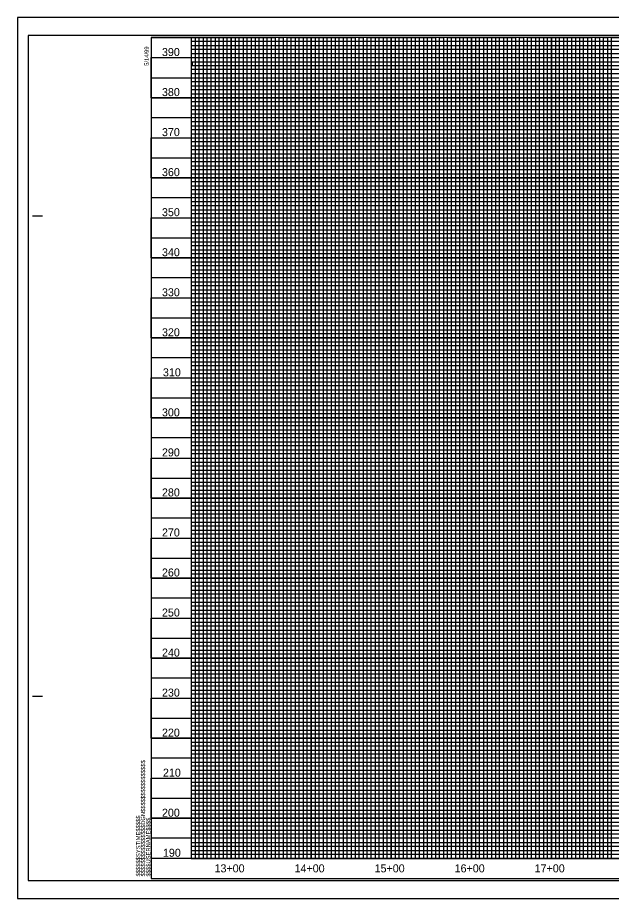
# Model space of a CAD drawing. Extents: x 10033 to 11717, y 9950 to 11050.
# Drawn here: x 10033 to 10775, y 9950 to 11050 of the extents above; entities that cross this region are included whole.
import ezdxf

# ---------------------------------------------------------------- set-up
doc = ezdxf.new("R2010")
doc.units = 0
for name, color, linetype in [('Exist Vertical Profile Horizontal Axis Label Major', 7, 'Continuous'), ('Exist Vertical Profile Vertical Axis Label', 7, 'Continuous'), ('Sheet Cutting Line CELL', 7, 'Continuous'), ('Sheet DOT Grid CELL', 7, 'Continuous'), ('Sheet Layout Profile Border', 7, 'Continuous'), ('Sheet Plot Border Inside CELL', 7, 'Continuous'), ('Sheet Plot Border Outside CELL', 7, 'Continuous'), ('Sheet Profile CELL', 7, 'Continuous'), ('Sheet Profile Grid Major CELL', 7, 'Continuous'), ('Sheet Profile Grid Middle CELL', 7, 'Continuous'), ('Sheet Profile Grid Minor CELL', 7, 'Continuous')]:
    doc.layers.add(name, color=color, linetype=linetype)

msp = doc.modelspace()

# ---------------------------------------------------------------- linework, layer by layer
at = {"layer": 'Sheet Cutting Line CELL'}
for p, q in [((11717, 11050), (10033, 11050)), ((10033, 11050), (10033, 9950)), ((10033, 9950), (11717, 9950))]:
    msp.add_line(p, q, dxfattribs=at)
at = {"layer": 'Sheet DOT Grid CELL'}
for p, q in [((10250, 11025), (10250, 10000)), ((10300, 11025), (10300, 10000)), ((10350, 11025), (10350, 10000)), ((10400, 11025), (10400, 10000)), ((10450, 11025), (10450, 10000)), ((10500, 11025), (10500, 10000)), ((10550, 11025), (10550, 10000)), ((10600, 11025), (10600, 10000)), ((10650, 11025), (10650, 10000)), ((10700, 11025), (10700, 10000)), ((10750, 11025), (10750, 10000)), ((10200, 11000), (11500, 11000)), ((10200, 10950), (11500, 10950)), ((10200, 10900), (11500, 10900)), ((10200, 10850), (11700, 10850)), ((10200, 10800), (11700, 10800)), ((10200, 10750), (11700, 10750)), ((10200, 10700), (11700, 10700)), ((10200, 10650), (11700, 10650)), ((10200, 10600), (11700, 10600)), ((10200, 10550), (11700, 10550)), ((10200, 10500), (11700, 10500)), ((10200, 10450), (11700, 10450)), ((10200, 10400), (11700, 10400)), ((10200, 10350), (11700, 10350)), ((10200, 10300), (11700, 10300)), ((10200, 10250), (11700, 10250)), ((10200, 10200), (11700, 10200)), ((10200, 10150), (11700, 10150)), ((10200, 10100), (11700, 10100)), ((10200, 10050), (11700, 10050))]:
    msp.add_line(p, q, dxfattribs=at)
at = {"layer": 'Sheet Layout Profile Border'}
msp.add_lwpolyline([(10250, 11025), (10250, 10000), (11650, 10000), (11650, 10887.5), (11500, 10887.5), (11500, 11025)], close=True, dxfattribs=at)
at = {"layer": 'Sheet Plot Border Inside CELL'}
msp.add_lwpolyline([(11712.5, 11027.6), (10046, 11027.6), (10046, 9972.5), (11712.5, 9972.5)], close=True, dxfattribs=at)
at = {"layer": 'Sheet Plot Border Outside CELL'}
msp.add_lwpolyline([(11717, 11050), (10033, 11050), (10033, 9950), (11717, 9950)], close=True, dxfattribs=at)
at = {"layer": 'Sheet Profile CELL'}
for p, q in [((10051.5, 10802.5), (10064, 10802.5)), ((10051.5, 10202.5), (10064, 10202.5)), ((11700, 10000), (10200, 10000)), ((10200, 9975), (10200, 9975)), ((10200, 9975), (10200, 9975)), ((10200, 9975), (10200, 9975)), ((10200, 9975), (10200, 9975)), ((10200, 9975), (10200, 9975)), ((10200, 9975), (10200, 9975))]:
    msp.add_line(p, q, dxfattribs=at)
msp.add_lwpolyline([(11700, 11025), (10200, 11025), (10200, 9975), (11700, 9975)], close=True, dxfattribs=at)
msp.add_lwpolyline([(10237.5, 9975), (10237.5, 9975)], dxfattribs=at)
at = {"layer": 'Sheet Profile Grid Major CELL'}
for points in [[(10200, 11025), (10250, 11025), (10250, 10000), (10300, 10000), (10300, 11025), (10350, 11025), (10350, 10000), (10400, 10000), (10400, 11025), (10450, 11025), (10450, 10000), (10500, 10000), (10500, 11025), (10550, 11025), (10550, 10000), (10600, 10000), (10600, 11025), (10650, 11025), (10650, 10000), (10700, 10000), (10700, 11025), (10750, 11025), (10750, 10000), (10800, 10000)], [(11500, 10950), (10200.1, 10950), (10200.1, 11000), (11500, 11000)], [(11700, 10850), (10200, 10850), (10200, 10900), (11500, 10900)], [(11700, 10750), (10200, 10750), (10200, 10800), (11700, 10800)], [(11700, 10650), (10200, 10650), (10200, 10700), (11700, 10700)], [(11700, 10550), (10200, 10550), (10200, 10600), (11700, 10600)], [(11700, 10450), (10200, 10450), (10200, 10500), (11700, 10500)], [(11700, 10350), (10200, 10350), (10200, 10400), (11700, 10400)], [(11700, 10250), (10200, 10250), (10200, 10300), (11700, 10300)], [(11700, 10150), (10200, 10150), (10200, 10200), (11700, 10200)], [(11700, 10050), (10200, 10050), (10200, 10100), (11700, 10100)]]:
    msp.add_lwpolyline(points, dxfattribs=at)
at = {"layer": 'Sheet Profile Grid Middle CELL'}
for points in [[(10275, 10000), (10275, 11025), (10325, 11025), (10325, 10000), (10375, 10000), (10375, 11025), (10425, 11025), (10425, 10000), (10475, 10000), (10475, 11025), (10525, 11025), (10525, 10000), (10575, 10000), (10575, 11025), (10625, 11025), (10625, 10000), (10675, 10000), (10675, 11025), (10725, 11025), (10725, 10000), (10775, 10000), (10775, 11025), (10825, 11025)], [(10200, 10975), (11500, 10975)], [(11500, 10925), (10200, 10925), (10200, 10875), (11700, 10875)], [(11700, 10825), (10200, 10825), (10200, 10775), (11700, 10775)], [(11700, 10725), (10200, 10725), (10200, 10675), (11700, 10675)], [(11700, 10625), (10200, 10625), (10200, 10575), (11700, 10575)], [(11700, 10525), (10200, 10525), (10200, 10475), (11700, 10475)], [(11700, 10425), (10200, 10425), (10200, 10375), (11700, 10375)], [(11700, 10325), (10200, 10325), (10200, 10275), (11700, 10275)], [(11700, 10225), (10200, 10225), (10200, 10175), (11700, 10175)], [(11700, 10125), (10200, 10125), (10200, 10075), (11700, 10075)], [(11700, 10025), (10200, 10025)]]:
    msp.add_lwpolyline(points, dxfattribs=at)
at = {"layer": 'Sheet Profile Grid Minor CELL'}
for p, q in [((11650, 10845), (10250, 10845)), ((10250, 10845), (10250, 10840)), ((10250, 10840), (11650, 10840)), ((11650, 10820), (10250, 10820))]:
    msp.add_line(p, q, dxfattribs=at)
for points in [[(10255, 11025), (10260, 11025), (10265, 11025), (10270, 11025), (10280, 11025), (10247, 11025), (10252, 11025), (10210, 11025), (10215, 11025), (10220, 11025), (10230, 11025), (10235, 11025), (10240, 11025), (10245, 11025), (10255, 11025), (10255, 10000), (10260, 10000), (10260, 11025), (10265, 11025), (10265, 10000), (10270, 10000), (10270, 11025), (10280, 11025), (10280, 10000), (10285, 10000), (10285, 11025), (10290, 11025), (10290, 10000), (10295, 10000), (10295, 11025), (10305, 11025), (10305, 10000), (10310, 10000), (10310, 11025), (10315, 11025), (10315, 10000), (10320, 10000), (10320, 11025), (10330, 11025), (10330, 10000), (10335, 10000), (10335, 11025), (10340, 11025), (10340, 10000), (10345, 10000), (10345, 11025), (10355, 11025), (10355, 10000), (10360, 10000), (10360, 11025), (10365, 11025), (10365, 10000), (10370, 10000), (10370, 11025), (10380, 11025), (10380, 10000), (10385, 10000), (10385, 11025), (10390, 11025), (10390, 10000), (10395, 10000), (10395, 11025), (10405, 11025), (10405, 10000), (10410, 10000), (10410, 11025), (10415, 11025), (10415, 10000)], [(10415, 10000), (10420, 10000), (10420, 11025), (10430, 11025), (10430, 10000), (10435, 10000), (10435, 11025), (10440, 11025), (10440, 10000), (10445, 10000), (10445, 11025), (10455, 11025), (10455, 10000), (10460, 10000), (10460, 11025), (10460, 11025), (10465, 11025), (10465, 10000), (10470, 10000), (10470, 11025), (10480, 11025), (10480, 10000), (10485, 10000), (10485, 11025), (10490, 11025), (10490, 10000), (10495, 10000), (10495, 11025), (10505, 11025), (10505, 10000), (10510, 10000), (10510, 11025), (10515, 11025), (10515, 10000), (10520, 10000), (10520, 11025), (10530, 11025), (10530, 10000), (10535, 10000), (10535, 11025), (10540, 11025), (10540, 10000), (10545, 10000), (10545, 11025), (10555, 11025), (10555, 10000), (10560, 10000), (10560, 11025), (10565, 11025), (10565, 10000), (10570, 10000), (10570, 11025), (10580, 11025), (10580, 10000), (10595, 10000), (10595, 11025), (10605, 11025), (10605, 10000), (10610, 10000), (10610, 11025), (10615, 11025), (10615, 10000), (10620, 10000), (10620, 11025), (10630, 11025), (10630, 10000), (10635, 10000), (10635, 11025), (10640, 11025), (10640, 10000), (10645, 10000), (10645, 11025), (10655, 11025), (10655, 10000), (10660, 10000), (10660, 11025), (10665, 11025), (10665, 10000), (10670, 10000), (10670, 11025), (10680, 11025), (10680, 10000), (10685, 10000), (10685, 11025), (10690, 11025), (10690, 10000), (10695, 10000), (10695, 11025), (10705, 11025), (10705, 10000), (10710, 10000), (10710, 11025), (10715, 11025), (10715, 10000), (10720, 10000), (10720, 11025), (10730, 11025), (10730, 10000)], [(10585, 11025), (10585, 10000), (10590, 10000), (10590, 11025)], [(10585, 11024.4), (10585, 10000), (10590, 10000), (10590, 11024.4)], [(10735, 11025), (10735, 10000), (10740, 10000), (10740, 11025), (10745, 11025), (10745, 10000), (10755, 10000), (10755, 11025), (10760, 11025), (10760, 10000), (10765, 10000), (10765, 11025), (10770, 11025), (10770, 10000)], [(11500, 11020), (10250, 11020), (10250, 11015), (11500, 11015)], [(11500, 11010), (10250, 11010), (10250, 11005), (11500, 11005)], [(11500, 10994.2), (10251, 10994.2), (10251, 10990), (11500, 10990)], [(11500, 10985), (10250, 10985), (10250, 10980), (11500, 10980)], [(11500, 10970), (10250, 10970), (10250, 10965), (11500, 10965)], [(11500, 10960), (10250, 10960), (10250, 10955), (11500, 10955)], [(11500, 10945), (10250, 10945), (10250, 10940), (11500, 10940)], [(11500, 10935), (10250, 10935), (10250, 10930), (11500, 10930)], [(11500, 10920), (10250, 10920), (10250, 10915), (11500, 10915)], [(11500, 10910), (10250, 10910), (10250, 10905), (11500, 10905)], [(11500, 10895), (10250, 10895), (10250, 10890), (11500, 10890)], [(11650, 10885), (10250, 10885), (10250, 10885), (10250, 10865), (11650, 10865)], [(10250, 10880), (11650, 10880)], [(11650, 10870), (10250, 10870)], [(11650, 10860), (10250, 10860), (10250, 10855), (11650, 10855)], [(11650, 10835), (10250, 10835), (10250, 10830), (11650, 10830)], [(11650, 10815), (10250, 10815), (10250, 10810), (11650, 10810)], [(11650, 10805), (10250, 10805)], [(10250, 10795), (11650, 10795)], [(11650, 10790), (10250, 10790), (10250, 10785), (11650, 10785)], [(11650, 10780), (10250, 10780), (10250, 10770), (11650, 10770)], [(11650, 10765), (10250, 10765), (10250, 10760), (11650, 10760)], [(11650, 10755), (10250, 10755), (10250, 10745), (11650, 10745)], [(11650, 10740), (10250, 10740), (10250, 10735), (11650, 10735)], [(11650, 10730), (10250, 10730), (10250, 10720), (11650, 10720)], [(11650, 10715), (10250, 10715), (10250, 10710), (11650, 10710)], [(11650, 10705), (10250, 10705), (10250, 10695), (11650, 10695)], [(11650, 10690), (10250, 10690), (10250, 10685), (11650, 10685)], [(11650, 10680), (10250, 10680), (10250, 10670), (11650, 10670)], [(11650, 10665), (10250, 10665), (10250, 10660), (11650, 10660)], [(11650, 10655), (10250, 10655), (10250, 10645), (11650, 10645)], [(11650, 10640), (10250, 10640), (10250, 10635), (11650, 10635)], [(11650, 10630), (10250, 10630), (10250, 10620), (11650, 10620)], [(11650, 10615), (10250, 10615), (10250, 10610), (11650, 10610)], [(11650, 10605), (10250, 10605), (10250, 10595), (11650, 10595)], [(11650, 10590), (10250, 10590), (10250, 10585), (11650, 10585)], [(11650, 10580), (10250, 10580), (10250, 10570), (11650, 10570)], [(11650, 10565), (10250, 10565), (10250, 10560), (11650, 10560)], [(11650, 10555), (10250, 10555), (10250, 10545), (11650, 10545)], [(11650, 10540), (10250, 10540), (10250, 10535), (11650, 10535)], [(11650, 10530), (10250, 10530), (10250, 10520), (11650, 10520)], [(11650, 10515), (10250, 10515), (10250, 10510), (11650, 10510)], [(11650, 10505), (10250, 10505)], [(10250, 10495), (11650, 10495)], [(11650, 10490), (10250, 10490), (10250, 10485), (11650, 10485)], [(11650, 10480), (10250, 10480), (10250, 10470), (11650, 10470)], [(11650, 10465), (10250, 10465), (10250, 10460), (11650, 10460)], [(11650, 10455), (10250, 10455), (10250, 10445), (11650, 10445)], [(11650, 10440), (10250, 10440), (10250, 10435), (11650, 10435)], [(11650, 10430), (10250, 10430), (10250, 10420), (11650, 10420)], [(11650, 10415), (10250, 10415), (10250, 10410), (11650, 10410)], [(11650, 10405), (10250, 10405), (10250, 10395), (11650, 10395)], [(11650, 10390), (10250, 10390), (10250, 10385), (11650, 10385)], [(11650, 10380), (10250, 10380), (10250, 10370), (11650, 10370)], [(11650, 10365), (10250, 10365), (10250, 10360), (11650, 10360)], [(11650, 10355), (10250, 10355), (10250, 10345), (11650, 10345)], [(11650, 10340), (10250, 10340), (10250, 10335), (11650, 10335)], [(11650, 10330), (10250, 10330), (10250, 10320), (11650, 10320)], [(11650, 10315), (10250, 10315), (10250, 10310), (11650, 10310)], [(11650, 10305), (10250, 10305), (10250, 10295), (11650, 10295)], [(11650, 10290), (10250, 10290), (10250, 10285), (11650, 10285)], [(11650, 10280), (10250, 10280), (10250, 10270), (11650, 10270)], [(11650, 10265), (10250, 10265), (10250, 10260), (11650, 10260)], [(11650, 10255), (10250, 10255), (10250, 10245), (11650, 10245)], [(11650, 10240), (10250, 10240), (10250, 10235), (11650, 10235)], [(11650, 10230), (10250, 10230), (10250, 10220), (11650, 10220)], [(11650, 10215), (10250, 10215), (10250, 10210), (11650, 10210)], [(11650, 10205), (10250, 10205)], [(10250, 10195), (11650, 10195)], [(11650, 10190), (10250, 10190), (10250, 10185), (11650, 10185)], [(11650, 10180), (10250, 10180)], [(10250, 10170), (11650, 10170)], [(11650, 10165), (10250, 10165), (10250, 10160), (11650, 10160)], [(11650, 10155), (10250, 10155), (10250, 10145), (11650, 10145)], [(11650, 10140), (10250, 10140), (10250, 10135), (11650, 10135)], [(11650, 10130), (10250, 10130), (10250, 10120), (11650, 10120)], [(11650, 10115), (10250, 10115), (10250, 10110), (11650, 10110)], [(11650, 10105), (10250, 10105), (10250, 10095), (11650, 10095)], [(11650, 10090), (10250, 10090), (10250, 10085), (11650, 10085)], [(11650, 10080), (10250, 10080), (10250, 10070), (11650, 10070)], [(11650, 10065), (10250, 10065), (10250, 10060), (11650, 10060)], [(11650, 10055), (10250, 10055), (10250, 10045), (11650, 10045)], [(11650, 10040), (10250, 10040), (10250, 10035), (11650, 10035)], [(11650, 10030), (10250, 10030), (10250, 10020), (11650, 10020)], [(11650, 10015), (10250, 10015), (10250, 10010), (11650, 10010)], [(11650, 10005), (10250, 10005)]]:
    msp.add_lwpolyline(points, dxfattribs=at)

# ---------------------------------------------------------------- texts
at = {"layer": 'Exist Vertical Profile Horizontal Axis Label Major'}
for s, p in [('13+00', (10279.1, 9982.5)), ('14+00', (10379.1, 9982.5)), ('15+00', (10479.1, 9982.5)), ('16+00', (10579.1, 9982.5)), ('17+00', (10679.1, 9982.5))]:
    msp.add_text(s, height=10, dxfattribs=at).set_placement(p)
at = {"layer": 'Exist Vertical Profile Vertical Axis Label'}
for s, p in [('390', (10213.4, 11002)), ('380', (10213.4, 10952)), ('370', (10213.4, 10902)), ('360', (10213.4, 10852)), ('350', (10213.4, 10802)), ('340', (10213.4, 10752)), ('330', (10213.4, 10702)), ('320', (10213.4, 10652)), ('310', (10214.6, 10602)), ('300', (10213.4, 10552)), ('290', (10213.4, 10502)), ('280', (10213.4, 10452)), ('270', (10213.4, 10402)), ('260', (10213.4, 10352)), ('250', (10213.4, 10302)), ('240', (10213.4, 10252)), ('230', (10213.4, 10202)), ('220', (10213.4, 10152)), ('210', (10214.6, 10102)), ('200', (10213.4, 10052)), ('190', (10214.6, 10002))]:
    msp.add_text(s, height=10, dxfattribs=at).set_placement(p)
at = {"layer": 'Sheet Profile CELL'}
for s, p in [('5/14/99', (10196.8, 10989.8)), ('$$$$$$$$$$$$$$$$DGN$$$$$$$$$$$$$$$$', (10192.4, 9977.4)), ('$$$$$$SYSTIME$$$$$', (10186.3, 9977.4)), ('$$$$USERNAME$$$$', (10198.9, 9977.4))]:
    msp.add_text(s, height=5.25, rotation=90, dxfattribs=at).set_placement(p)

doc.saveas('drawing.dxf')
